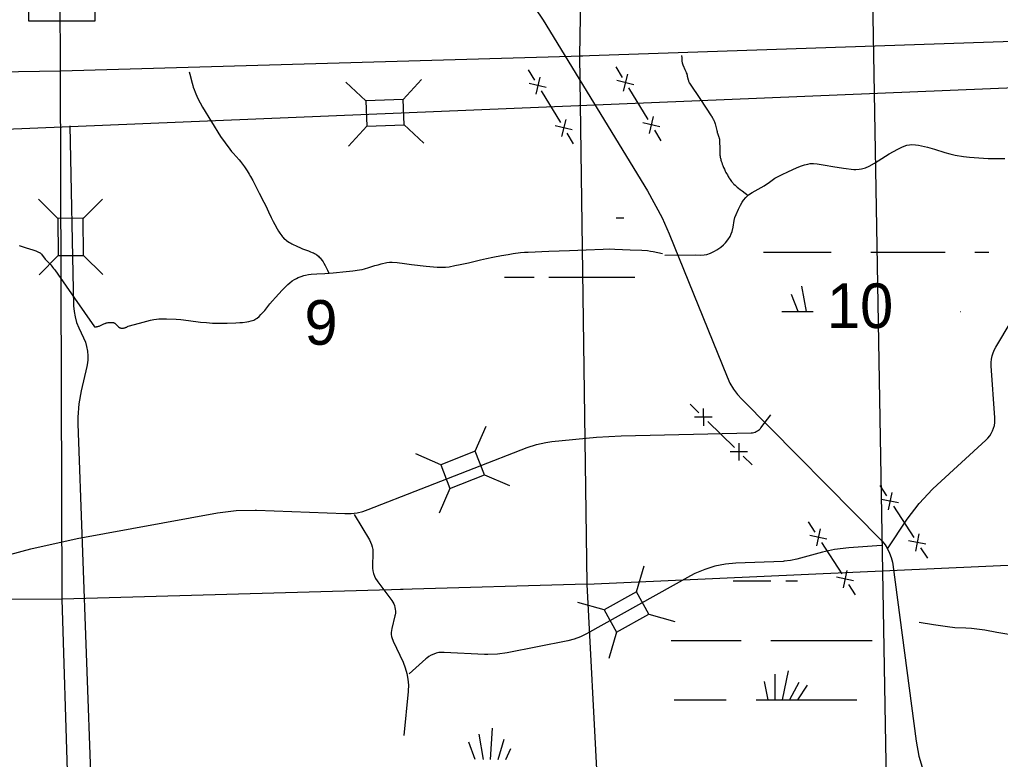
# Model space of a CAD drawing. Extents: x 2480962 to 2688785, y 277103 to 599240.
# Drawn here: x 2591923 to 2601822, y 422119 to 429582 of the extents above; entities that cross this region are included whole.
import ezdxf

# ---------------------------------------------------------------- set-up
doc = ezdxf.new("R2010")
doc.units = 0
for name, color, linetype in [('Divided_Highway', 7, 'Continuous'), ('Level 31', 7, 'Continuous'), ('Local Roads Improved', 7, 'Continuous'), ('Narrow River Creek and Branch and Slough', 7, 'Continuous'), ('Section Lines', 7, 'Continuous'), ('Section Numbers', 7, 'Continuous'), ('Swamps', 7, 'Continuous'), ('Uninventoried Roads and Features', 7, 'Continuous')]:
    doc.layers.add(name, color=color, linetype=linetype)

msp = doc.modelspace()

# ---------------------------------------------------------------- linework, layer by layer
at = {"layer": 'Divided_Highway'}
msp.add_line((2600799.421, 414762.355), (2600001.432, 460214.017), dxfattribs=at)
at = {"layer": 'Level 31'}
msp.add_lwpolyline([(2592013.2, 429570.681), (2592683.969, 429570.681), (2592683.969, 430453.861), (2592013.2, 430453.861)], close=True, dxfattribs=at)
at = {"layer": 'Local Roads Improved'}
for p, q in [((2597208.28, 429576.265), (2598259.628, 427855.128)), ((2598477.933, 427421.9), (2599063.807, 425976.807)), ((2599213.398, 425753.612), (2600629.892, 424319.882)), ((2600735.655, 424084.391), (2600971.863, 422303.194))]:
    msp.add_line(p, q, dxfattribs=at)
for points in [[(2596621.012, 430359.212), (2596962.539, 429942.344), (2597208.28, 429576.265)], [(2598259.628, 427855.128), (2598407.885, 427581.145), (2598477.933, 427421.9)], [(2599063.807, 425976.807), (2599093.035, 425914.322), (2599128.636, 425855.235), (2599170.217, 425800.192), (2599213.398, 425753.612)], [(2600629.892, 424319.882), (2600658.834, 424282.593), (2600683.721, 424242.482), (2600704.279, 424199.99), (2600720.281, 424155.583), (2600731.555, 424109.745), (2600735.655, 424084.391)], [(2600971.863, 422303.194), (2600999.864, 422152.907), (2601043.42, 422006.369), (2601056.462, 421971.099)]]:
    msp.add_lwpolyline(points, dxfattribs=at)
at = {"layer": 'Narrow River Creek and Branch and Slough'}
for points in [[(2598604.949, 429219.269), (2598605.518, 429198.312), (2598606.089, 429177.356), (2598606.328, 429172.62), (2598606.741, 429168.205), (2598607.963, 429159.985), (2598609.456, 429152.85), (2598611.038, 429146.648), (2598614.307, 429135.874), (2598617.069, 429127.851), (2598626.031, 429104), (2598629.497, 429095.198), (2598636.022, 429080.038), (2598646.218, 429057.562), (2598651.171, 429046.292), (2598655.826, 429034.908), (2598657.879, 429029.193), (2598659.569, 429023.731), (2598662.267, 429013.28), (2598670.238, 428976.099), (2598672.752, 428967.06), (2598674.989, 428960.446), (2598676.913, 428955.601), (2598680.27, 428948.553), (2598682.188, 428945.141), (2598684.282, 428941.811), (2598793.624, 428777.451), (2598902.967, 428613.092)], [(2593634.993, 429056.902), (2593641.988, 429031.138), (2593664.664, 428940.205), (2593670.839, 428917.684), (2593675.835, 428900.947), (2593684.102, 428876.167), (2593693.533, 428851.876), (2593720.078, 428793.44), (2593745.705, 428743.317), (2593769.596, 428700.077), (2593949.582, 428402.761)], [(2598902.967, 428613.092), (2598905.579, 428609.505), (2598907.794, 428606.323), (2598911.507, 428600.654), (2598914.154, 428596.312), (2598916.06, 428593.004), (2598918.791, 428587.952), (2598921.365, 428582.79), (2598925.705, 428573.402), (2598929.291, 428565.129), (2598935.112, 428550.517), (2598939.115, 428539.446), (2598941.92, 428531.081), (2598945.826, 428518.431), (2598949.386, 428505.661), (2598953.489, 428489.312), (2598959.219, 428464.704), (2598962.101, 428452.418), (2598965.125, 428440.179), (2598966.431, 428435.455), (2598969.292, 428426.667), (2598980.672, 428396.156), (2598983.109, 428388.468), (2598984.646, 428382.657), (2598985.595, 428378.266), (2598986.627, 428371.617), (2598987.114, 428364.881), (2598987.956, 428333.945), (2598988.798, 428303.009), (2598989.937, 428261.094), (2598991.078, 428219.181), (2598991.304, 428214.226), (2598992.188, 428204.987), (2598993.403, 428196.957), (2598994.763, 428189.967), (2598996.152, 428183.877), (2598998.959, 428173.273), (2599001.318, 428165.36), (2599005.135, 428153.543), (2599009.136, 428141.778), (2599015.456, 428124.145), (2599020.466, 428111.119), (2599028.426, 428091.801), (2599036.939, 428072.632), (2599045.738, 428054.044), (2599052.603, 428040.291), (2599057.917, 428030.068), (2599066.176, 428014.857), (2599074.814, 427999.767), (2599080.469, 427990.339), (2599085.561, 427982.205), (2599094.854, 427968.263), (2599102.195, 427958.085), (2599107.938, 427950.627), (2599116.977, 427939.751), (2599121.705, 427934.463), (2599126.581, 427929.281), (2599132.683, 427923.074), (2599143.554, 427912.513), (2599151.873, 427904.822), (2599164.621, 427893.614), (2599177.697, 427882.745), (2599195.906, 427868.092), (2599205.088, 427860.877), (2599214.377, 427853.789), (2599244.91, 427831.183), (2599260.319, 427820.084), (2599275.875, 427809.179)], [(2593949.582, 428402.761), (2593996.165, 428338.9), (2594043.579, 428275.723), (2594061.672, 428253.019), (2594078.215, 428233.722), (2594138.042, 428167.706), (2594152.698, 428150.953), (2594173.849, 428125.148), (2594183.913, 428111.83), (2594193.552, 428098.167), (2594207.737, 428076.672), (2594219.702, 428057.615), (2594239.791, 428023.788), (2594254.283, 427998.095), (2594275.361, 427959.184), (2594295.986, 427920.011), (2594342.343, 427831.067), (2594387.855, 427741.72), (2594407.084, 427702.519), (2594435.304, 427643.415), (2594463.634, 427584.339), (2594483.729, 427544.321), (2594499.412, 427514.68), (2594524.001, 427470.687), (2594536.809, 427448.85), (2594549.978, 427427.091), (2594559.305, 427412.932), (2594568.165, 427401.059), (2594576.429, 427391.083), (2594584.038, 427382.683), (2594590.975, 427375.593), (2594597.252, 427369.593), (2594608.687, 427359.565), (2594617.623, 427352.452), (2594631.576, 427342.456), (2594646.154, 427333.303), (2594659.136, 427325.897), (2594670.557, 427319.701), (2594690.693, 427309.428), (2594705.929, 427302.137), (2594729.016, 427291.748), (2594752.406, 427281.867), (2594778.853, 427271.394), (2594818.738, 427256.388), (2594838.674, 427248.825), (2594858.538, 427240.986), (2594876.541, 427233.65), (2594889.829, 427227.831), (2594899.613, 427223.046), (2594906.824, 427219.118), (2594912.15, 427215.939), (2594919.99, 427210.73), (2594923.837, 427207.903), (2594927.632, 427204.913), (2594938.182, 427195.808), (2594947.494, 427186.887), (2594955.745, 427178.208), (2594963.084, 427169.811), (2594975.892, 427153.445), (2594986.178, 427138.532), (2594994.554, 427125.087), (2595008.017, 427100.822), (2595017.299, 427082.137), (2595030.273, 427053.589), (2595042.558, 427024.743)], [(2598435.487, 427207.185), (2598745.082, 427208.318), (2598794.721, 427206.323), (2598831.098, 427208.176), (2598857.898, 427213.525), (2598897.57, 427226.818), (2598936.913, 427245.068), (2598961.817, 427258.94), (2599001.661, 427286.433), (2599028.477, 427309.815), (2599046.898, 427328.947), (2599071.857, 427360.274), (2599093.671, 427394.835), (2599106.132, 427421.489), (2599114.085, 427445.593), (2599123.64, 427488.889), (2599135.016, 427554.392), (2599142.924, 427586.393), (2599154.497, 427617.28), (2599178.772, 427671.136), (2599198.093, 427711.214), (2599214.301, 427740.104), (2599227.881, 427760.695), (2599251.229, 427789.225), (2599279.013, 427814.141), (2599317.592, 427839.637), (2599377.611, 427872.073), (2599407.439, 427888.213), (2599436.441, 427905.859), (2599491.054, 427943.998), (2599546.513, 427981.142), (2599613.806, 428017.964), (2599683.057, 428051.484), (2599763, 428086.967), (2599803.89, 428102.646), (2599846.071, 428116.882), (2599877.51, 428125.13), (2599901.348, 428129.191), (2599937.19, 428131.552), (2599972.722, 428129.039), (2600052.09, 428114.612), (2600131.552, 428099.38), (2600237.291, 428082.898), (2600343.205, 428070.389), (2600362.568, 428069.529), (2600396.397, 428071.94), (2600421.642, 428076.736), (2600459.148, 428088.171), (2600496.021, 428103.99), (2600549.995, 428133.393), (2600624.969, 428181.319), (2600662.158, 428205.216), (2600700.624, 428227.97), (2600788.109, 428276.566), (2600832.902, 428297.935), (2600879.243, 428314.676), (2600904.254, 428320.022), (2600926.598, 428321.983), (2600966.381, 428320.466), (2600996.486, 428316.195), (2601085.492, 428296.17), (2601155.682, 428276.489), (2601259.994, 428242.42), (2601312.713, 428227.111), (2601366.425, 428215.273), (2601449.524, 428202.415), (2601511.954, 428194.909), (2601605.732, 428186.895), (2601699.63, 428182.538), (2601794.636, 428181.066), (2601865.979, 428181.844)], [(2591919.405, 427302.286), (2591959.631, 427289.371), (2591999.866, 427276.529), (2592014.332, 427272.098), (2592065.232, 427257.731), (2592077.816, 427253.638), (2592087.165, 427250.246), (2592101.007, 427244.487), (2592107.831, 427241.246), (2592114.579, 427237.728), (2592119.99, 427234.517), (2592124.799, 427231.215), (2592129.096, 427227.888), (2592136.673, 427221.12), (2592142.871, 427214.725), (2592182.341, 427165.683), (2592194.424, 427152.453), (2592237.409, 427106.767), (2592247.852, 427095.116), (2592255.491, 427086.223), (2592266.539, 427072.563), (2592276.983, 427058.421), (2592478.159, 426771.185), (2592679.336, 426483.95)], [(2593018.194, 426489.344), (2593131.425, 426519.805), (2593244.657, 426550.266), (2593276.179, 426557.272), (2593304.147, 426561.315), (2593328.85, 426563.484), (2593372.44, 426564.789), (2593405.292, 426564.196), (2593503.421, 426558.817), (2593549.052, 426555.39), (2593628.848, 426546.504), (2593748.525, 426531.201), (2593808.416, 426525.001), (2593868.377, 426521.209), (2593927.703, 426520.059), (2594016.883, 426521.294), (2594106.075, 426524.216), (2594144.501, 426525.907), (2594173.235, 426527.973), (2594216.217, 426533.188), (2594237.659, 426537.066), (2594259.075, 426541.985), (2594273.456, 426546.44), (2594285.574, 426551.408), (2594305.755, 426562.227), (2594320.047, 426571.876), (2594340.156, 426588.336), (2594358.704, 426606.581), (2594396.401, 426648.803), (2594450.093, 426713.463), (2594476.963, 426745.662), (2594504.654, 426777.323), (2594574.611, 426853.968), (2594611.294, 426891.066), (2594630.631, 426909.181), (2594650.847, 426926.956), (2594674.569, 426945.353), (2594696.381, 426959.578), (2594716.175, 426970.631), (2594733.97, 426979.259), (2594766.018, 426992.079), (2594790.663, 426999.846), (2594809.408, 427004.662), (2594837.822, 427010.313), (2594866.441, 427014.131), (2594921.863, 427018.408), (2595005.097, 427022.16), (2595046.674, 427024.291), (2595088.17, 427027.491), (2595220.269, 427040.177), (2595286.212, 427047.759), (2595351.973, 427057.218), (2595380.102, 427062.653), (2595404.396, 427068.568), (2595446.452, 427080.712), (2595509.29, 427100.527), (2595541.001, 427109.879), (2595573.153, 427118.074), (2595628.423, 427130.788), (2595656.129, 427134.856), (2595670.004, 427135.633), (2595683.895, 427135.309), (2595732.806, 427130.7), (2595806.191, 427120.88), (2595879.64, 427111.395), (2596027.702, 427094.473), (2596101.79, 427087.479), (2596138.812, 427085.007), (2596175.807, 427083.472), (2596200.308, 427083.661), (2596221.717, 427085.088), (2596259.121, 427089.844), (2596315.097, 427100.471), (2596370.942, 427112.331), (2596452.916, 427130.196), (2596575.011, 427158.76), (2596636.148, 427172.506), (2596697.643, 427185.077), (2596786.85, 427201.996), (2596853.89, 427213.873), (2596904.283, 427221.805), (2596980.108, 427231.355), (2597018.146, 427234.777), (2597056.282, 427237.115), (2597264.869, 427245.255), (2597473.449, 427252.947), (2597642.416, 427260.563), (2597811.387, 427267.778), (2597880.063, 427268.668), (2597931.589, 427267.619), (2598086.18, 427260.697), (2598203.084, 427256.128), (2598261.263, 427251.425), (2598290.147, 427247.622), (2598318.84, 427242.528), (2598365.619, 427233.004), (2598412.397, 427223.479)], [(2592679.336, 426483.95), (2592684.792, 426483.826), (2592689.595, 426483.921), (2592693.812, 426484.156), (2592697.507, 426484.474), (2592703.974, 426485.275), (2592708.812, 426486.073), (2592712.428, 426486.778), (2592717.822, 426488.001), (2592723.166, 426489.415), (2592727.587, 426490.777), (2592731.665, 426492.218), (2592739.164, 426495.278), (2592745.601, 426498.251), (2592767.687, 426509.517), (2592773.214, 426512.237), (2592781.595, 426516.003), (2592785.847, 426517.69), (2592790.152, 426519.214), (2592794.883, 426520.676), (2592799.409, 426521.897), (2592808.092, 426523.81), (2592815.846, 426525.096), (2592822.708, 426525.938), (2592828.743, 426526.467), (2592839.296, 426526.95), (2592847.14, 426526.964), (2592852.948, 426526.79), (2592861.485, 426526.247), (2592869.744, 426525.39), (2592872.321, 426524.943), (2592874.765, 426524.286), (2592877.086, 426523.452), (2592881.461, 426521.332), (2592885.432, 426518.811), (2592889.056, 426516.048), (2592892.377, 426513.164), (2592898.447, 426507.175), (2592908.768, 426495.776), (2592916.455, 426487.396), (2592919.364, 426484.471), (2592924.528, 426479.818), (2592928.485, 426476.828), (2592931.514, 426474.929), (2592933.826, 426473.725), (2592937.365, 426472.311), (2592941.002, 426471.417), (2592945.386, 426470.79), (2592949.68, 426470.364), (2592953.845, 426470.115), (2592957.852, 426470.022), (2592965.575, 426470.235), (2592972.481, 426470.865), (2592978.573, 426471.779), (2592983.901, 426472.874), (2592988.532, 426474.067), (2592992.542, 426475.3), (2592999.416, 426477.898), (2593004.41, 426480.231), (2593008.042, 426482.205), (2593013.271, 426485.541), (2593018.194, 426489.344)], [(2601003.511, 423502.712), (2601146.405, 423480.767), (2601289.298, 423458.822), (2601363.033, 423450.625), (2601474.361, 423444.635), (2601529.999, 423441.418), (2601585.406, 423436.174), (2601666.316, 423424.422), (2601787.15, 423402.813), (2601908.29, 423382.196)]]:
    msp.add_lwpolyline(points, dxfattribs=at)
at = {"layer": 'Section Lines'}
for p, q in [((2597649.454, 434538.797), (2597574.807, 429216.543)), ((2592335.094, 429085.254), (2592320.257, 434417.727)), ((2597574.805, 429216.543), (2608323.435, 429578.678)), ((2592335.062, 429066.942), (2597606.232, 429217.441)), ((2597574.805, 429216.543), (2597647.054, 423885.1)), ((2587043.962, 428976.191), (2592335.408, 429066.949)), ((2592353.376, 423734.308), (2592335.144, 429066.944)), ((2603173.215, 424132.31), (2597647.134, 423883.6)), ((2597647.054, 423885.1), (2595769.007, 423831.585)), ((2597647.134, 423883.6), (2597928.766, 418560.806)), ((2595793.509, 423832.283), (2592353.379, 423734.256)), ((2592353.376, 423734.308), (2587082.407, 423718.078)), ((2592517.637, 418479.185), (2592353.379, 423734.256))]:
    msp.add_line(p, q, dxfattribs=at)
at = {"layer": 'Swamps'}
for p, q in [((2592335.144, 429066.944), (2592334.789, 429194.299)), ((2600514.953, 427237.864), (2601264.956, 427237.874)), ((2599865.472, 426637.929), (2599819.216, 426892.311)), ((2599780.398, 426638.016), (2599714.924, 426809.882)), ((2599126.053, 423919.004), (2599505.821, 423919.013)), ((2598755.83, 423318.992), (2599205.829, 423319.002)), ((2599679.684, 423013.819), (2599620.747, 422719.112)), ((2599438.04, 422905.073), (2599475.251, 422719.026)), ((2599546.779, 422977.569), (2599546.783, 422719.006)), ((2599788.425, 422892.998), (2599694.42, 422718.409)), ((2599873.001, 422868.835), (2599773.683, 422719.853)), ((2598755.839, 422718.988), (2599055.838, 422718.995)), ((2596677.36, 422118.97), (2596694.596, 422435.047)), ((2596606.36, 422119.018), (2596560.105, 422373.401)), ((2596754.046, 422119.15), (2596812.278, 422322.971)), ((2596521.286, 422119.106), (2596455.813, 422290.971)), ((2596830.642, 422119.073), (2596879.525, 422227.707))]:
    msp.add_line(p, q, dxfattribs=at)
for points in [[(2597944.985, 427584.112), (2598022.896, 427584.114)], [(2599431.111, 427237.841), (2600114.954, 427237.856)], [(2601564.957, 427237.877), (2601705.469, 427237.878)], [(2596816.057, 426984.084), (2597115.565, 426984.091)], [(2597265.565, 426984.094), (2598133.18, 426984.113)], [(2599614.963, 426637.841), (2599933.678, 426637.848)], [(2601414.965, 426637.872), (2601418.758, 426637.872)], [(2599655.82, 423919.016), (2599774.439, 423919.018)], [(2598497.63, 423318.986), (2598755.83, 423318.992)], [(2599505.829, 423319.009), (2600528.179, 423319.031)], [(2598529.63, 422718.983), (2598755.839, 422718.988)], [(2599355.837, 422719.002), (2600373.539, 422719.024)]]:
    msp.add_lwpolyline(points, dxfattribs=at)
at = {"layer": 'Uninventoried Roads and Features'}
for p, q in [((2578841.335, 427942.49), (2613676.151, 429381.289)), ((2597055.557, 429076.798), (2597120.718, 428970.126)), ((2597939.218, 429106.713), (2598004.379, 429000.041)), ((2598057.715, 429032.622), (2598016.204, 428860.788)), ((2595418.092, 428763.166), (2595216.281, 428949.909)), ((2595792.811, 428777.698), (2595979.554, 428979.51)), ((2597239.215, 428896.034), (2597067.382, 428937.545)), ((2597174.054, 429002.707), (2597132.543, 428830.873)), ((2598122.876, 428925.949), (2597951.043, 428967.46)), ((2597185.879, 428863.454), (2597381.363, 428543.437)), ((2598069.54, 428893.369), (2598265.024, 428573.352)), ((2595792.811, 428777.698), (2595418.092, 428763.166)), ((2595418.092, 428763.166), (2595428.013, 428507.358)), ((2595802.732, 428521.89), (2595792.811, 428777.698)), ((2597434.699, 428576.018), (2597393.188, 428404.184)), ((2598383.522, 428499.261), (2598211.688, 428540.772)), ((2598318.36, 428605.933), (2598276.849, 428434.099)), ((2592430.886, 428510.739), (2592468.321, 426696.04)), ((2595428.013, 428507.358), (2595241.27, 428305.546)), ((2595428.013, 428507.358), (2595802.732, 428521.89)), ((2595801.339, 428523.179), (2596003.15, 428336.436)), ((2597499.861, 428469.346), (2597328.027, 428510.857)), ((2597446.525, 428436.765), (2597511.686, 428330.093)), ((2598330.186, 428466.68), (2598395.347, 428360.008)), ((2592309.969, 427576.719), (2592114.403, 427769.992)), ((2592564.63, 427576.88), (2592757.903, 427772.446)), ((2592565.964, 427578.23), (2592309.969, 427576.719)), ((2592309.969, 427576.719), (2592312.182, 427201.726)), ((2592568.177, 427203.237), (2592565.964, 427578.23)), ((2592312.182, 427201.726), (2592118.909, 427006.16)), ((2592312.182, 427201.726), (2592568.177, 427203.237)), ((2592568.177, 427203.237), (2592763.743, 427009.964)), ((2592520.645, 426473.44), (2592569.194, 426370.612)), ((2601775.987, 426277.202), (2601931.45, 426536.309)), ((2592600.178, 426082.65), (2592543.287, 425836.056)), ((2601766.187, 425563.392), (2601730.4, 426087.747)), ((2598690.712, 425702.526), (2598780.011, 425615.058)), ((2598913.044, 425572.24), (2598736.277, 425570.409)), ((2598823.745, 425659.708), (2598825.577, 425482.941)), ((2599405.463, 425463.755), (2599505.151, 425594.737)), ((2592511.668, 425505.162), (2592706.629, 420124.604)), ((2596522.369, 425228.738), (2596632.385, 425480.724)), ((2598869.311, 425527.591), (2599137.209, 425265.188)), ((2597294.914, 425324.791), (2597745.099, 425368.832)), ((2597993.806, 425383.795), (2599307.01, 425413.564)), ((2595441.827, 424638.85), (2597045.384, 425265.072)), ((2599180.943, 425309.837), (2599182.775, 425133.07)), ((2601182.545, 424889.517), (2601676.307, 425339.524)), ((2596173.257, 425091.823), (2595921.271, 425201.839)), ((2596522.369, 425228.738), (2596173.257, 425091.823)), ((2596615.837, 424990.411), (2596522.369, 425228.738)), ((2599270.242, 425222.37), (2599093.475, 425220.538)), ((2599226.509, 425177.72), (2599315.808, 425090.252)), ((2596173.257, 425091.823), (2596266.725, 424853.496)), ((2596266.725, 424853.496), (2596615.837, 424990.411)), ((2596614.098, 424991.17), (2596866.084, 424881.154)), ((2600604.924, 424881.221), (2600673.58, 424776.764)), ((2596266.725, 424853.496), (2596156.709, 424601.509)), ((2600725.809, 424811.092), (2600690.008, 424637.978)), ((2600794.465, 424706.634), (2600621.351, 424742.436)), ((2600742.236, 424672.306), (2600948.205, 424358.934)), ((2592504.598, 424347.68), (2593921.383, 424604.963)), ((2594313.827, 424632.854), (2595206.674, 424599.142)), ((2595299.224, 424590.613), (2595452.994, 424335.188)), ((2599883.51, 424516.797), (2599950.86, 424411.494)), ((2600683.495, 424242.893), (2600882.842, 424541.153)), ((2600070.863, 424339.865), (2599898.208, 424377.818)), ((2600003.512, 424445.169), (2599965.559, 424272.515)), ((2601000.433, 424393.262), (2600964.632, 424220.149)), ((2600018.211, 424306.19), (2600220.262, 423990.279)), ((2600621.745, 424277.115), (2600293.191, 424253.772)), ((2601069.089, 424288.805), (2600895.976, 424324.606)), ((2588644.688, 423336.167), (2592035.35, 424242.539)), ((2595489.197, 424196.18), (2595485.3, 424075.663)), ((2600026.943, 424208.605), (2599767.899, 424138.263)), ((2601016.861, 424254.477), (2601085.517, 424150.019)), ((2599628.862, 424116.917), (2599153.552, 424098.122)), ((2598150.346, 423808.37), (2598225.86, 424072.753)), ((2600272.914, 424023.954), (2600234.961, 423851.3)), ((2595537.931, 423909.386), (2595678.734, 423722.398)), ((2598694.453, 423969.404), (2597644.211, 423385.816)), ((2600340.265, 423918.65), (2600167.61, 423956.604)), ((2600287.613, 423884.975), (2600354.963, 423779.671)), ((2598150.346, 423808.37), (2597822.552, 423626.226)), ((2598274.69, 423584.596), (2598150.346, 423808.37)), ((2597822.552, 423626.226), (2597558.169, 423701.74)), ((2597822.552, 423626.226), (2597946.896, 423402.452)), ((2597946.896, 423402.452), (2598274.69, 423584.596)), ((2598272.865, 423585.117), (2598537.249, 423509.603)), ((2595710.762, 423567.68), (2595679.415, 423437.996)), ((2597946.896, 423402.452), (2597871.382, 423138.068)), ((2595692.371, 423311.68), (2595793.038, 423098.73)), ((2597454.807, 423316.26), (2596844.673, 423194.668)), ((2596614.215, 423177.86), (2596209.729, 423198.547)), ((2596021.453, 423131.668), (2595855.448, 422981.991)), ((2595844.86, 422802.632), (2595802.599, 422359.358))]:
    msp.add_line(p, q, dxfattribs=at)
for points in [[(2592468.321, 426696.04), (2592472.503, 426638.849), (2592482.64, 426582.409), (2592498.62, 426527.337), (2592520.27, 426474.238), (2592520.645, 426473.44)], [(2592569.194, 426370.612), (2592586.724, 426327.816), (2592599.684, 426283.423), (2592607.932, 426237.918), (2592611.379, 426191.8), (2592609.985, 426145.575), (2592603.769, 426099.748), (2592600.178, 426082.65)], [(2601730.4, 426087.747), (2601729.862, 426121.782), (2601732.886, 426155.686), (2601739.436, 426189.089), (2601749.443, 426221.625), (2601762.796, 426252.935), (2601775.987, 426277.202)], [(2592543.287, 425836.056), (2592520.263, 425705.374), (2592511.027, 425573.003), (2592511.668, 425505.162)], [(2601676.307, 425339.524), (2601696.71, 425360.176), (2601714.842, 425382.846), (2601730.506, 425407.287), (2601743.529, 425433.233), (2601753.769, 425460.396), (2601761.113, 425488.482), (2601765.481, 425517.181), (2601766.825, 425546.181), (2601766.187, 425563.392)], [(2599307.01, 425413.564), (2599320.301, 425414.563), (2599333.417, 425416.945), (2599346.211, 425420.687), (2599358.545, 425425.745), (2599370.282, 425432.064), (2599381.294, 425439.576), (2599391.461, 425448.198), (2599400.671, 425457.834), (2599405.463, 425463.755)], [(2597745.099, 425368.832), (2597993.806, 425383.795)], [(2597045.384, 425265.072), (2597138.452, 425295.908), (2597234.233, 425316.846), (2597294.914, 425324.791)], [(2600882.842, 424541.153), (2601001.811, 424700.43), (2601136.778, 424846.399), (2601182.545, 424889.517)], [(2593921.383, 424604.963), (2594109.668, 424629.058), (2594299.441, 424633.339), (2594313.827, 424632.854)], [(2595206.674, 424599.142), (2595267.973, 424600.038), (2595328.843, 424607.337), (2595388.617, 424620.959), (2595441.827, 424638.85)], [(2592035.35, 424242.539), (2592504.598, 424347.68)], [(2595452.994, 424335.188), (2595465.476, 424311.758), (2595475.442, 424287.153), (2595482.78, 424261.64), (2595487.413, 424235.499), (2595489.287, 424209.018), (2595489.197, 424196.18)], [(2600293.191, 424253.772), (2600148.529, 424235.846), (2600026.943, 424208.605)], [(2599153.552, 424098.122), (2599046.31, 424088.241), (2598940.689, 424067.204), (2598837.844, 424035.241), (2598738.904, 423992.703), (2598694.453, 423969.404)], [(2599767.899, 424138.263), (2599703.978, 424124.452), (2599638.964, 424117.399), (2599628.862, 424116.917)], [(2595485.3, 424075.663), (2595485.85, 424048.21), (2595489.267, 424020.966), (2595495.512, 423994.227), (2595504.519, 423968.288), (2595516.188, 423943.433), (2595530.39, 423919.933), (2595537.931, 423909.385)], [(2595678.734, 423722.398), (2595689.555, 423706.344), (2595698.638, 423689.247), (2595705.884, 423671.294), (2595711.214, 423652.682), (2595714.569, 423633.614), (2595715.913, 423614.301), (2595715.231, 423594.953), (2595712.529, 423575.782), (2595710.762, 423567.68)], [(2595679.415, 423437.996), (2595675.747, 423418.374), (2595674.15, 423398.475), (2595674.642, 423378.519), (2595677.216, 423358.723), (2595681.846, 423339.305), (2595688.481, 423320.477), (2595692.371, 423311.68)], [(2597644.211, 423385.816), (2597582.856, 423355.812), (2597518.701, 423332.387), (2597454.807, 423316.26)], [(2596209.729, 423198.547), (2596182.385, 423198.512), (2596155.194, 423195.62), (2596128.456, 423189.901), (2596102.461, 423181.419), (2596077.495, 423170.265), (2596053.831, 423156.563), (2596031.729, 423140.463), (2596021.453, 423131.668)], [(2596844.673, 423194.668), (2596747.838, 423180.592), (2596650.064, 423176.716), (2596614.215, 423177.86)], [(2595793.038, 423098.73), (2595815.555, 423043.827), (2595832.212, 422986.871), (2595842.823, 422928.486), (2595847.273, 422869.312), (2595845.514, 422809.997), (2595844.86, 422802.632)]]:
    msp.add_lwpolyline(points, dxfattribs=at)

# ---------------------------------------------------------------- texts
at = {"layer": 'Section Numbers'}
for s, rotation, p in [('10', 0.0289889, (2600071.319, 426470.423)), ('9', 0.0291667, (2594797.606, 426301.978))]:
    msp.add_text(s, height=450, rotation=rotation, dxfattribs=at).set_placement(p)

doc.saveas('drawing.dxf')
